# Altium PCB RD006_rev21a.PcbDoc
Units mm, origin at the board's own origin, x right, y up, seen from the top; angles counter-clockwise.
Board outline 20 x 20 mm, 2 copper layers (Top Layer, Bottom Layer), stack 1.569 mm thick; 25 components, 13 nets, 53 pads, 30 vias.
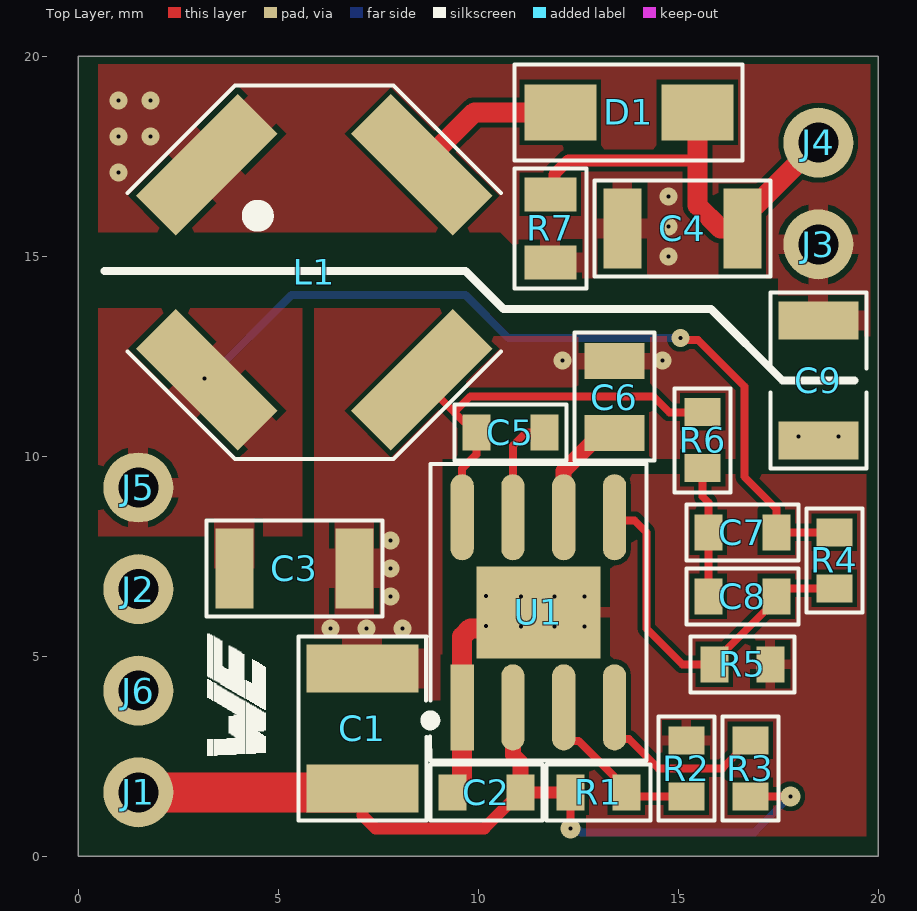
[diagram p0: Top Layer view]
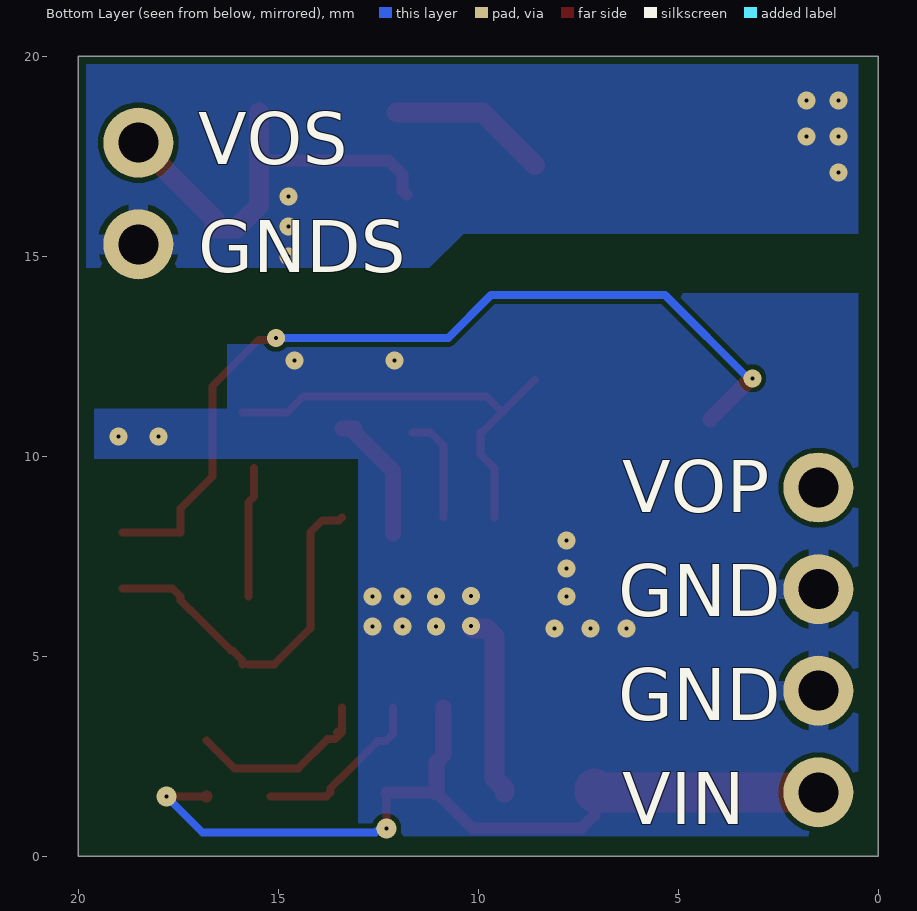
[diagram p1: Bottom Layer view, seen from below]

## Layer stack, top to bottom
Top Solder: solder mask 0.025, SM-001, Dk 4
Top Layer: signal copper 0.035
Dielectric 1: core 1.499, Core-043, Dk 4.3
Bottom Layer: signal copper 0.035
Bottom Solder: solder mask 0.025, SM-001, Dk 4

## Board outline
0,0 20,0 20,20 0,20

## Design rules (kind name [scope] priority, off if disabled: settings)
AcuteAngle [All] p1 off: minimum=4.50000000000000E+0001 checktracksonly=FALSE
AssemblyTestPointUsage [All] p1 off: valid=2
AssemblyTestpoint [All] p1 off: testpointundercomponent=TRUE minsize=1.016 maxsize=2.54 preferedsize=1.524 minholesize=0 maxholesize=1.016 preferedholesize=0.813 testpointgrid=0.025 usegrid=TRUE gridtolerance=0 allowsidetop=TRUE allowsidebottom=TRUE
Clearance Clearance_WEDirekt_125u_35u [All] p1: gap=0.125 ignorepadtopadclearanceinfootprint=TRUE except(0.17: SMDPad-SMDPad SMDPad-THPad THPad-THPad)
ComponentClearance "Schematic Component Clearance Constraint 2" [InComponent('NT1')] p1: gap=0 collisioncheckmode=3 verticalgap=0 showdistances=FALSE
ComponentClearance "Schematic Component Clearance Constraint 1" [InComponent('NT2')] p2: gap=0 collisioncheckmode=3 verticalgap=0 showdistances=FALSE
ComponentClearance ComponentClearance_ScrewToNut [(HasFootprint('NY PMS 440 0025 PH')) vs (HasFootprint('Keystone_1902C'))] p3: gap=0 collisioncheckmode=3 verticalgap=0 showdistances=FALSE
ComponentClearance ComponentClearance_testpoint [(HasFootprint('NO BOM TP'))] p4: gap=0 collisioncheckmode=3 verticalgap=0 showdistances=FALSE
ComponentClearance not_comp_1 [WithinRoom('not_comp')] p5: gap=0 collisioncheckmode=3 verticalgap=0 showdistances=FALSE
ComponentClearance ComponentClearance_1 [All] p6: gap=0.254 collisioncheckmode=3 verticalgap=0.254 showdistances=FALSE
ComponentClearance ComponentClearance_Shunt [InComponentClass('Header') vs InComponentClass('Shunt')] p7 off: gap=0 collisioncheckmode=3 verticalgap=0 showdistances=FALSE
ComponentClearance ComponentClearance_Logo [InComponentClass('Logo')] p8: gap=1.27 collisioncheckmode=3 verticalgap=0.254 showdistances=FALSE
ComponentClearance ComponentClearance_MountingHoles [InComponentClass('Mounting Holes')] p9: gap=0 collisioncheckmode=3 verticalgap=2540 showdistances=FALSE
ComponentClearance ComponentClearance_SmallPassives [HasFootprint('0201*') or HasFootprint('0402*') or HasFootprint('0508') or HasFootprint('0603*') or HasFootprint('0612') or HasFootprint('0805*') or HasFootprint('0815*') or HasFootprint('0830*') or HasFootprint('1206*') or HasFootprint('1210*') or HasFootprint('1808*') or HasFootprint('1812*') or HasFootprint('1825*') or HasFootprint('2010*') or HasFootprint('2220*') or HasFootprint('2225*') or HasFootprint('2512*') or HasFootprint('2728*') or HasFootprint('3518*') vs HasFootprint('0201*') or HasFootprint('0402*') or HasFootprint('0508') or HasFootprint('0603*') or HasFootprint('0612') or HasFootprint('0805*') or HasFootprint('0815*') or HasFootprint('0830*') or HasFootprint('1206*') or HasFootprint('1210*') or HasFootprint('1808*') or HasFootprint('1812*') or HasFootprint('1825*') or HasFootprint('2010*') or HasFootprint('2220*') or HasFootprint('2225*') or HasFootprint('2512*') or HasFootprint('2728*') or HasFootprint('3518*')] p10: gap=0.127 collisioncheckmode=3 verticalgap=0.254 showdistances=FALSE
ComponentClearance ComponentClearance_THtoSMT [IsThruComponent vs IsSMTComponent] p11: gap=1.016 collisioncheckmode=3 verticalgap=0.762 showdistances=FALSE
ComponentClearance ComponentClearance_THtoTH [IsThruComponent vs IsThruComponent] p12: gap=3 collisioncheckmode=3 verticalgap=0.762 showdistances=FALSE
DiffPairsRouting [All] p1 off: maxlimit=2.54 minlimit=0.254 mostfreqgap=0.254 toplayer_minwidth=0.381 toplayer_maxwidth=0.381 toplayer_prefwidth=0.381 bottomlayer_minwidth=0.381 bottomlayer_maxwidth=0.381 bottomlayer_prefwidth=0.381 maxuncoupledlength=25.4
FabricationTestPointUsage TestPointUsage [All] p1: valid=2 allowmultiple=FALSE
FabricationTestpoint Testpoint [All] p1: side=3 testpointundercomponent=TRUE minsize=1.016 maxsize=2.54 preferedsize=1.524 minholesize=0 maxholesize=1.016 preferedholesize=0.813 testpointgrid=0.025 allowsidetop=TRUE allowsidebottom=TRUE usegrid=TRUE gridtolerance=0
FanoutControl Fanout_LCC [IsLCC] p1 off: bgadir=Out bgaviamode=Centered fanoutstyle=Auto fanoutdirection=Alternating viagrid=0.025 // Fanout_LCC (Default Rule)
FanoutControl Fanout_BGA [IsBGA] p2: bgadir=Out bgaviamode=Centered fanoutstyle=Auto fanoutdirection=Alternating viagrid=0.025 // Fanout_BGA (Default Rule)
FanoutControl Fanout_Default [All] p4: bgadir=Out bgaviamode=Centered fanoutstyle=Auto fanoutdirection=Alternating viagrid=0.025 // Fanout_Default (Default Rule)
FanoutControl Fanout_Small [(CompPinCount < 5)] p5: bgadir=Out bgaviamode=Centered fanoutstyle=Auto fanoutdirection=OutThenIn viagrid=0.025 // Fanout_Small (Default Rule)
Height [All] p1 off: minheight=0 maxheight=25.4 prefheight=12.7
HoleSize [All] p1: absolutevalues=TRUE maxlimit=1000 minlimit=0.1 maxpercent=80.000 minpercent=20.000
HoleToHoleClearance [All] p1: gap=0.4 allowstackedmicrovias=TRUE
MinimumAnnularRing MinimumAnnularRing_ThermalPadVias [IsVia and InAnyComponent] p1: minimumring=0.174
MinimumAnnularRing [All] p2: minimumring=0.174
MinimumSolderMaskSliver MinimumSolderMaskSliver_Logo [InComponentClass('Logo') vs InComponentClass('Logo')] p1: minsoldermaskwidth=0.018
MinimumSolderMaskSliver [All] p2: minsoldermaskwidth=0.025
PlaneConnect [All] p1: planeconnectstyle=Direct reliefexpansion=0.254 reliefentries=4 reliefconductorwidth=0.254 reliefairgap=0.254
PolygonConnect PolygonConnect_1 [InNet('GND')] p1: connectstyle=Relief reliefconductorwidth=0.254 reliefentries=4 polygonreliefangle="90 Angle" airgapwidth=0.254
PolygonConnect [All] p2: connectstyle=Direct reliefconductorwidth=0.254 reliefentries=4 polygonreliefangle="90 Angle" airgapwidth=0.254
RoutingVias Vias_WEDirekt_125u_35u [IsVia and InAnyComponent] p1: holewidth=0.1 width=0.45 viastyle="Through Hole" minholewidth=0.1 minwidth=0.45 maxholewidth=1 maxwidth=20
RoutingVias [All] p2: holewidth=0.1 width=0.45 viastyle="Through Hole" minholewidth=0.1 minwidth=0.45 maxholewidth=20 maxwidth=20
SMDToCorner [All] p1: distance=30000
SilkToSilkClearance [All] p1 off: silktosilkclearance=0.127
SilkToSolderMaskClearance SilkscreenOverComponentPads [IsPad] p1 off: minsilkscreentomaskgap=0.127 clearancetoexposedcopper=TRUE
SolderMaskExpansion [All] p1: expansion=0.1 istentingtop=FALSE
UnRoutedNet [All] p1: checkbadconnections=TRUE
Width Width_WEDirekt_125u_35u [All] p1: maxlimit=20 minlimit=0.125 preferedwidth=0.5 minimp=50.000000 maximp=50.000000 favimp=50.000000 checkconnectedcopper=TRUE
12 further rules are at their usual default settings.

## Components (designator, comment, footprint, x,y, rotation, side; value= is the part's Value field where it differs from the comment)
C1 "885012209048" C1210 7.1,3.2 r270 top value=4.7u
C2 "885012206121" C0603 10.2,1.6 r0 top value=330n
C3 "885012208019" C1206 5.4,7.2 r180 top value=22u
C4 "885012208019" C1206 15.1,15.7 r180 top value=22u
C5 "885012206065" C0603 10.8,10.6 r180 top value=10n
C6 "885012207023" C0805 13.4,11.48 r270 top value=1.5u
C7 "885012206087" C0603 16.6,8.1 r0 top value=4.7n
C8 "885012206095" C0603 16.6,6.5 r180 top value=100n
C9 "885342208024" C1206 18.5,11.9 r90 top value=1n
D1 "SS1FN6-M3" D_DO-219AB_(SMF) 13.7,18.6 r0 top
J1 "Pin_hole_1mm" J_PIN-TH-ROUND-1MM#1 1.5,1.6 r90 top
J2 "Pin_hole_1mm" J_PIN-TH-ROUND-1MM#2 1.5,7.067 r90 top
J3 "Pin_hole_1mm" J_PIN-TH-ROUND-1MM#1 18.5,15.3 r90 top
J4 "Pin_hole_1mm" J_PIN-TH-ROUND-1MM#3 18.5,18.1 r90 top
J5 "Pin_hole_1mm" J_PIN-TH-ROUND-1MM#4 1.5,9.8 r90 top
J6 "Pin_hole_1mm" J_PIN-TH-ROUND-1MM#5 1.5,4.333 r90 top
L1 "76889440330" "WE-TDC HV_8038" 5.9,14.6 r45 top value="33 uH"
R1 "RC0603FR-07127KL" R0603 13,1.6 r180 top value=127k
R2 "RC0603FR-0715K4L" R0603 15.2,2.2 r270 top value=15.4k
R3 "RT0603BRD07120KL" R0603 16.8,2.2 r90 top value=120k
R4 "RT0603DRE074K7L" R0603 18.9,7.4 r90 top value=4.7k
R5 "RT0603DRD071K5L" R0603 16.6,4.8 r180 top value=1.5k
R6 "RC0603FR-1033KL" R0603 15.61,10.41 r270 top value=33k
R7 "RCS0805300RJNEA" R0805 11.8,15.7 r270 top value=300
U1 "LM25017" IC_SOIC-8-DDA0008J 11.5,6.1 r90 top

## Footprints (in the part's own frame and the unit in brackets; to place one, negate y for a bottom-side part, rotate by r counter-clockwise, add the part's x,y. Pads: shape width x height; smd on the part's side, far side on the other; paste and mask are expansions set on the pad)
C0603 [mm] "R0603"
  rect 0.7x0.9 smd: 1(-0.85,0) 2(0.85,0)
  body extent -0.8,-0.4 0.8,0.4, height 0.6
C0805 [mm] "Chip Capacitor, 2-Leads, Body 2.00x1.25mm, IPC Low Density"
  rect 0.9x1.5 smd: 1(-0.9,0) 2(0.9,0)
  body extent -1.1,-0.72 1.1,0.72, height 1.45
C1206 [mm]
  rect 0.95x2 smd: 1(-1.5,0) 2(1.5,0)
  body extent -1.7,-0.9 1.7,0.9, height 1.8
C1210 [mm] "Chip Capacitor, Body 3.2x2.5mm, Height 2.8mm, IPC High Density"
  rect 1.2x2.8 smd: 1(-1.5,0) 2(1.5,0)
  body extent -1.7,-1.4 1.7,1.4, height 2.8
D_DO-219AB_(SMF) [mm]
  rect 1.8x1.4 smd: A(-1.651,0) C(1.778,0)
  body extent -1.95,-0.95 1.95,0.95, height 1.08
IC_SOIC-8-DDA0008J [mm]
  rect 2.153x0.582 smd paste+0 mask+0: 1(-2.377,1.905)
  rrect100% 2.153x0.582 smd paste+0 mask+0: 2(-2.377,0.635) 3(-2.377,-0.635) 4(-2.377,-1.905) 5(2.377,-1.905) 6(2.377,-0.635) 7(2.377,0.635) 8(2.377,1.905)
  rect 2.3x3.1 smd paste-1000 mask+0: 9(0,0)
  silkscreen extent -2.82,2.57 -2.58,2.82, body extent -3.7,-2.7 3.7,2.7, height 0.25
J_PIN-TH-ROUND-1MM#1 [mm] "PIN-TH-ROUND-1MM"
  round 1.75 / inner round 1.524 / far side round 1.75 hole 1: 1(0,0)
J_PIN-TH-ROUND-1MM#2 [mm] "PIN-TH-ROUND-1MM"
  round 1.75 / inner round 1.524 / far side round 1.75 hole 1: 1(-0.387,0)
J_PIN-TH-ROUND-1MM#3 [mm] "PIN-TH-ROUND-1MM"
  round 1.75 / inner round 1.524 / far side round 1.75 hole 1: 1(-0.26,0)
J_PIN-TH-ROUND-1MM#4 [mm] "PIN-TH-ROUND-1MM"
  round 1.75 / inner round 1.524 / far side round 1.75 hole 1: 1(-0.58,0)
J_PIN-TH-ROUND-1MM#5 [mm] "PIN-TH-ROUND-1MM"
  round 1.75 / inner round 1.524 / far side round 1.75 hole 1: 1(-0.193,0)
R0603 [mm] "Chip Resistor, Body 1.6x0.8mm, IPC High Density"
  rect 0.7x0.9 smd: 1(-0.7,0) 2(0.7,0)
  body extent -0.85,-0.47 0.85,0.47, height 0.6
R0805 [mm] "Chip Resistor, Body 2.0x1.3mm, IPC High Density"
  rect 0.85x1.3 smd: 1(-0.85,0) 2(0.85,0)
  body extent -1.1,-0.67 1.1,0.68, height 0.7
"WE-TDC HV_8038" [mm] "SMD Coupled Inductor, 4-leads, body 8x8mm"
  rect 3.6x1.4 smd: 1(0,3.8) 3(0,-3.8)
  rect 1.4x3.6 smd: 2(-3.8,0) 4(3.8,0)
  silkscreen extent -0.2,1.8 0.2,2.2, body extent -4,-4 4,4, height 3.8

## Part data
C1: "MLCC WCAP-CSGP General Purpose 4.7uF 10% 50V X7R SMD-1210 885012209048", Dielectric=X7R, MFR="Wurth Elektronik", Package=1210, Tolerance=10%, Voltage=50V
C2: "MLCC WCAP-CSGP General Purpose 330nF 10% 50V X7R SMD-0603 885012206121", Dielectric=X7R, MFR="Wurth Elektronik", Package=0603, Tolerance=10%, Voltage=50V
C3 C4: "MLCC WCAP-CSGP General Purpose 22uF 10% 10V X7R SMD-1206 885012208019", Dielectric=X7R, MFR="Wurth Elektronik", Package=1206, Tolerance=10%, Voltage=10V
C5: "MLCC WCAP-CSGP General Purpose 10nF 10% 25V X7R SMD-0603 885012206065", Dielectric=X7R, MFR="Wurth Elektronik", Package=0603, Tolerance=10%, Voltage=25V
C6: "MLCC WCAP-CSGP General Purpose 1.5uF 10% 10V X7R SMD-0805 885012207023", Dielectric=X7R, MFR="Wurth Elektronik", Package=0805, Tolerance=10%, Voltage=10V
C7: "MLCC WCAP-CSGP General Purpose 4.7nF 10% 50V X7R SMD-0603 885012206087", Dielectric=X7R, MFR="Wurth Elektronik", Package=0603, Tolerance=10%, Voltage=50V
C8: "MLCC WCAP-CSGP General Purpose 100nF 10% 50V X7R SMD-0603 885012206095", Dielectric=X7R, MFR="Wurth Elektronik", Package=0603, Tolerance=10%, Voltage=50V
C9: "MLCC WCAP-CSGP HIgh-voltage 1nF 10% 2000V X7R SMD-1206 885342208024", Dielectric=X7R, MFR="Wurth Elektronik", Package=1206, Tolerance=10%, Voltage=2000V
D1: "Schottky Rectifier 1A 60V SMD SMF (DO-219AB) SS1FN6-M3", Current=1A, MFR=Vishay, Package="DO-219AB (SMF)", Voltage=60V
J1 J2 J3 J4 J5 J6: "Pin Hole 1mm"
L1: library part "TDC-HV 8038 76889440330", "TDC-HV 8038 33uH 1.85A 1:1 SMD Coupled Inductor 76889440330", MFR="Wurth Elektronik"
R1: "Thick Film 127k 1% 100mW SMD-0603 RC0603FR-07127KL", MFR=Yageo, Package=0603, Power=100mW, Tolerance=1%
R2: "Thick Film 15.4k 1% 100mW SMD-0603 RC0603FR-0715K4L", MFR=Yageo, Package=0603, Power=100mW, Tolerance=1%
R3: "Thin Film 120k 0.1% 100mW SMD-0603 RT0603BRD07120KL", MFR=Yageo, Package=0603, Power=100mW, Tolerance=0.1%
R4: "Thin Film 4.7k 0.1% 100mW SMD-0603 RT0603DRE074K7L", MFR=Yageo, Package=0603, Power=100mW, Tolerance=0.1%
R5: "Thin Film 1.5k 0.1% 100mW SMD-0603 RT0603DRD071K5L", MFR=Yageo, Package=0603, Power=100mW, Tolerance=0.1%
R6: "Thick Film 33k 1% 100mW SMD-0603 RC0603FR-1033KL", MFR=Yageo, Package=0603, Power=100mW, Tolerance=1%
R7: "Thick Film 300 5% 400mW SMD-0805 RCS0805300RJNEA", MFR=Yageo, Package=0603, Power=400mW, Tolerance=5%
U1: "IC Synchronous Buck/Flybuck Controller 48V 0.65A LM25017 SMD SOIC-8 Texas Instruments", MFR="Texas Instruments", Package=SOIC-8

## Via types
v1: diameter 0.45, hole 0.1, Top Layer to Bottom Layer, 28 vias
v2: diameter 0.5, hole 0.1, Top Layer to Bottom Layer, 2 vias

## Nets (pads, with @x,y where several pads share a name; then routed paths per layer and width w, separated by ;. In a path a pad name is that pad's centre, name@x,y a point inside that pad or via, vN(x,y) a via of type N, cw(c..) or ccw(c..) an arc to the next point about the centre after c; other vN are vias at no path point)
BST: C5.1 U1.7 | length 2.7
  Top Layer w0.2: U1.7 10.865,10.265 11.2,10.6 C5.1
DSEC: D1.A L1.4 | length 4
  Top Layer w0.5: L1.4 9.9,18.6 D1.A
FB: C8.1 R4.1 R5.2 U1.5 | length 9.2
  Top Layer w0.2: U1.5 13.482,8.4 13.9,8.4 14.2,8.1 14.2,5.7 15.1,4.8 R5.2@15.75,4.8 ; R5.2 15.9,4.9 16.15,5.15 16.187,5.15 17.187,6.15 17.2,6.15 17.45,6.4 C8.1 17.65,6.7 R4.1
GND: C1.1 C2.1 C3.1 C6.1 C9.1 J2.1 J6.1 R2.1 R5.1 U1.1 U1.9 | length 4.7
  Top Layer w0.2: U1.9@10.136,5.7 v1(10.188,5.752)
  Top Layer w0.5: C2.1 9.35,1.7 9.595,1.945 U1.1 9.595,5.495 9.8,5.7 U1.9@10.136,5.7
  other v1: 6.3,5.7 7.2,5.7 8.1,5.7 11.064,5.747 11.9,5.75 12.65,5.75 7.8,6.5 10.188,6.502 11.064,6.497 11.9,6.5 12.65,6.5 7.8,7.2 7.8,7.9 18,10.5 19,10.5 12.1,12.4 14.6,12.4
GND_ISO: C4.2 C9.2 J3.1 L1.1 R7.2
  other v1: 14.75,15 14.75,15.75 14.75,16.5 1,17.1 1,18 1.8,18 1,18.9 1.8,18.9
RON: R3.2 U1.4 | length 4.7
  Top Layer w0.2: U1.4 13.405,3.104 13.582,2.928 13.772,2.928 14.5,2.2 16.1,2.2 R3.2 ; U1.4@13.505,3.123 U1.4@13.528,3.1
SW: C5.2 L1.3 R6.1 U1.8 | length 11
  Top Layer w0.2: L1.3 9.4,11.1 ; U1.8 9.595,9.695 9.95,10.05 C5.2 9.9,10.6 9.4,11.1 ; R6.1@15.9,11.1 14.776,11.1 14.376,11.5 9.8,11.5 9.4,11.1
UVLO: R1.1 R2.2 U1.3 | length 4.4
  Top Layer w0.2: U1.3 12.135,3.064 12.312,2.887 12.502,2.887 13.44,1.95 13.45,1.95 13.7,1.7 R1.1 13.8,1.5 R2.2
VCC: C6.2 U1.6 | length 3.2
  Top Layer w0.4: U1.6@12.135,8.077 12.135,9.635 C6.2@13.1,10.6 ; C6.2@13.1,10.7 C6.2@13.4,10.7
VIN: C1.2 C2.2 J1.1 R1.2 R3.1 U1.2 | length 22
  Top Layer w0.2: v2(12.3,0.7) R1.2 ; R3.1 v2(17.8,1.5)
  Top Layer w0.3: C1.2@7.1,1.6 7.1,1.024 7.424,0.7 10.15,0.7 C2.2 R1.2
  Top Layer w0.4: U1.2 10.865,2.535 11.05,2.35 C2.2
  Top Layer w1: J1.1 7.1,1.6 C1.2
  Bottom Layer w0.2: v2(12.3,0.7) 12.357,0.643 12.525,0.643 12.567,0.6 16.9,0.6 v2(17.8,1.5)
VOUT: C3.2 C7.2 J5.1 L1.2 R4.2 | length 22.1
  Top Layer w0.2: v1(15.06,12.96) 15.108,12.912 15.488,12.912 16.65,11.75 16.65,9.49 17.45,8.69 C7.2 R4.2
  Top Layer w0.4: L1.2 L1.2@4.2,10.926
  Bottom Layer w0.2: v1@3.2,11.9 5.33,14.03 9.68,14.03 10.75,12.96 v1(15.06,12.96)
  other v1: 3.15,11.95
VOUT_ISO: C4.1 D1.C J4.1 R7.1 | length 10.9
  Top Layer w0.3: R7.1 11.9,16.65 11.9,17.051 12.249,17.4 15.478,17.4
  Top Layer w0.5: D1.C 15.478,17.4 15.478,16.271 16.049,15.7 C4.1 16.6,15.94 J4.1
VR: C7.1 C8.2 R6.2 | length 3.3
  Top Layer w0.2: R6.2 15.61,8.99 15.75,8.85 C7.1 C8.2

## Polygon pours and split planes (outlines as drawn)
GND on Bottom Layer "GND_BOT_PWR" (solid, pour order 78): 9.634,14.076 10.91,12.8 16.275,12.8 16.275,11.19 19.6,11.19 19.6,9.933 13,9.933 13,0.5 0.5,0.5 0.5,14.076
GND_ISO on Bottom Layer "GND_ISO_BOT" (solid, pour order 72): 0.5,15.57 10.365,15.57 11.225,14.71 18.25,14.71 19.8,14.71 19.8,19.8 0.5,19.8
GND on Top Layer "GND_TOP_SGN" (solid, remove dead copper, pour order 77): 12.7,9.55 19.7,9.55 19.7,0.5 14.6,0.5 12.7,0.5
GND on Top Layer "GND_TOP_PWR" (solid, pour order 79): 9.1,9.933 9.1,3.9 5.9,3.9 5.9,13.7 9.4,13.7 10.1,13 16.9,13 16.9,11.9 16.9,9.933
VOUT on Top Layer "VOUT_TOP" (solid, pour order 76): 0.5,8 5.6,8 5.6,13.7 0.5,13.7
GND_ISO on Top Layer "GND_ISO_TOP" (solid, pour order 71): 0.5,15.6 10.545,15.6 11.695,14.45 17.5,14.45 17.5,13 19.8,13 19.8,19.8 0.5,19.8

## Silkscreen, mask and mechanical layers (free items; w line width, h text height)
Top Overlay:
  drawing of 251 lines, arcs and shapes, not listed
Bottom Overlay:
  text "VOS" at 17,17.3 h1.3
  text "GNDS" at 17,14.6 h1.3
  text "VOP" at 6.4,8.6 h1.3
  text "GND" at 6.5,6 h1.3
  text "GND" at 6.5,3.4 h1.3
  text "VIN" at 6.4,0.8 h1.3
Board Outline:
  the board outline again, w0.1
Dimensions:
  text "Dimensions in MM" at -5.2,25.3 h2
  text "Dimensions" at 1.58,-20.6 h2
Bottom Reference_Assembly:
  lines w0.127: 340.9,27.585 345.98,27.585 ; 340.9,98.07 345.98,98.07 ; 340.9,168.555 345.98,168.555
  text "A" at 342.805,201.626 h1.78
  text "B" at 342.805,131.014 h1.78
  text "C" at 342.805,60.402 h1.78
  text "D" at 342.805,-9.702 h1.78
Drill Drawing:
  circle w0.254: c-13.693,47.421 r0.866
  lines w0.254: -14.558,50.45 -12.827,50.45 -12.827,52.182 -14.558,52.182 -14.558,50.45
  lines w0.381: -16.11,45.386 164.248,45.386 ; -16.11,53.177 164.248,53.177 ; -1.821,41.491 -1.821,57.073 ; 12.188,41.491 12.188,57.073 ; 40.477,41.491 40.477,57.073 ; 53.597,41.491 53.597,57.073 ; 72.636,41.491 72.636,57.073 ; 111.569,41.491 111.569,57.073 ; 126.87,41.491 126.87,57.073 ; 146.221,41.491 146.221,57.073 ; -16.11,41.491 164.248,41.491 164.248,57.073 -16.11,57.073 -16.11,41.491
  text "Symbol" at -13.772,54.346 h1.87
  text "Count" at -0.652,54.346 h1.87
  text "Hole Size" at 13.357,54.346 h1.87
  text "Plated" at 41.646,54.346 h1.87
  text "Hole Type" at 54.765,54.346 h1.87
  text "Drill Layer Pair" at 73.805,54.346 h1.87
  text "Via/Pad" at 112.738,54.346 h1.87
  text "Pad Shape" at 128.039,54.346 h1.87
  text "Template" at 147.389,54.346 h1.87
  text "6" at -0.652,50.45 h1.56
  text "1.000mm (39.37mil)" at 13.357,50.45 h1.56
  text "PTH" at 41.646,50.45 h1.56
  text "Round" at 54.765,50.45 h1.56
  text "Top Layer - Bottom Layer" at 73.805,50.45 h1.56
  text "Pad" at 112.738,50.45 h1.56
  text "Rounded" at 128.039,50.45 h1.56
  text "(Mixed)" at 147.389,50.45 h1.56
  text "30" at -0.652,46.555 h1.56
  text "0.100mm (3.94mil)" at 13.357,46.555 h1.56
  text "PTH" at 41.646,46.555 h1.56
  text "Round" at 54.765,46.555 h1.56
  text "Top Layer - Bottom Layer" at 73.805,46.555 h1.56
  text "Via" at 112.738,46.555 h1.56
  text "Rounded" at 128.039,46.555 h1.56
  text "(Mixed)" at 147.389,46.555 h1.56
  text "36 Total" at -0.652,42.659 h1.56
  text "DRILL Guide" at 5.28,-20.65 h2
Sheet:
  drawing of 1218 lines, arcs and shapes, not listed
  text "1" at -23.683,235.611 h1.78
  text "2" at 25.356,235.611 h1.78
  text "3" at 74.615,235.611 h1.78
  text "4" at 123.908,235.611 h1.78
  text "5" at 173.184,235.611 h1.78
  text "6" at 222.206,235.611 h1.78
  text "7" at 271.736,235.611 h1.78
  text "8" at 320.758,235.611 h1.78
  text "A" at -45.815,201.626 h1.78
  text "B" at -45.815,131.014 h1.78
  text "C" at -45.815,60.402 h1.78
  text "D" at -45.815,-9.702 h1.78
  text "TITLE:" at 200.28,-18.9 h2
  text "RD006 board" at 211.28,-18.9 h2
  text "Eleazar Falco" at 215.28,-24.65 h2
  text "ENGINEER:" at 200.28,-24.9 h2
  text "August 21" at 210.28,-30.9 h2
  text "DATE:" at 200.28,-31 h2
  text "N/A" at 213.53,-36.4 h2
  text "REV:" at 232.78,-36.4 h2
  text "21a" at 240.53,-36.4 h2
  text "N/A" at 280.53,-36.4 h2
  text "VERSION:" at 200.28,-36.5 h2
  text "ASSY VARIANT:" at 258.18,-36.5 h2
  text "1" at -23.683,-41.249 h1.78
  text "2" at 25.356,-41.249 h1.78
  text "3" at 74.615,-41.249 h1.78
  text "4" at 123.908,-41.249 h1.78
  text "5" at 173.184,-41.249 h1.78
  text "6" at 222.206,-41.249 h1.78
  text "7" at 271.736,-41.249 h1.78
  text "8" at 320.758,-41.249 h1.78
Gerber Print:
  drawing of 1652 lines, arcs and shapes, not listed
  text "ARTWORK VIEWED FROM TOP SIDE OF BOARD" at -1.47,-12.4 h1.6
  text "BOARD NAME:" at -11.72,-16.65 h2
  text "RD006 Board" at 11.28,-16.65 h2
  text "LAYER:" at -11.72,-20.9 h2
  text "REV:" at 21.78,-24.9 h2
  text "21a" at 31.78,-24.9 h2
  text "VERSION:" at -11.72,-25.15 h2
  text "N/A" at 4.78,-25.15 h2
  text "DATE:" at -11.72,-29.4 h2
  text "August 21" at -0.8,-30.2 h2
  text "(c) Wurth Elektronik eiSos Group        www.we-online.de" at -12.72,-33.9 h2
Assembly Notes:
  drawing of 365 lines, arcs and shapes, not listed
  text "FABRICATION NOTES" at 247.33,214.6 h3
  text "Layer" at -14.721,212.024 h1.72
  text "Name" at -3.068,212.024 h1.72
  text "Material" at 34.874,212.024 h1.72
  text "Thickness" at 57.958,212.024 h1.72
  text "Constant" at 76.469,212.024 h1.72
  text "Board Layer Stack" at 92.694,212.024 h1.72
  text "Top Overlay" at -3.068,208.594 h1.72
  text "Top Solder" at -3.068,205.163 h1.72
  text "SM-001" at 34.874,205.163 h1.72
  text "0.025mm" at 57.958,205.163 h1.72
  text "4" at 76.469,205.163 h1.72
  text "MINIMUM SIZE CONSTRAINTS" at 248.03,204.6 h2
  text "Top Surface Finish" at -3.068,201.733 h1.72
  text "Nickel, Gold" at 34.874,201.733 h1.72
  text "0.004mm" at 57.958,201.733 h1.72
  text "1" at -14.721,198.303 h1.72
  text "Top Layer" at -3.068,198.303 h1.72
  text "CF-004" at 34.874,198.303 h1.72
  text "0.035mm" at 57.958,198.303 h1.72
  text "TRACK WIDTH (MIN):" at 217.03,196.6 h2
  text "0.2 mm" at 255.03,196.6 h2
  text "CLEARANCE (MIN):" at 277.03,196.6 h2
  text "0.125 mm" at 312.03,196.6 h2
  text "Dielectric 1" at -3.068,194.873 h1.72
  text "Core-043" at 34.874,194.873 h1.72
  text "1.499mm" at 57.958,194.873 h1.72
  text "4.3" at 76.469,194.873 h1.72
  text "2" at -14.721,191.443 h1.72
  text "Bottom Layer" at -3.068,191.443 h1.72
  text "CF-004" at 34.874,191.443 h1.72
  text "0.035mm" at 57.958,191.443 h1.72
  text "DRILL DIAM.(MIN):" at 217.03,188.6 h2
  text "0.1 mm" at 255.03,188.6 h2
  text "PAD SIZE (MIN):" at 277.03,188.6 h2
  text "XXXX mm" at 312.03,188.6 h2
  text "Bottom Surface Finish" at -3.068,188.013 h1.72
  text "Nickel, Gold" at 34.874,188.013 h1.72
  text "0.004mm" at 57.958,188.013 h1.72
  text "Bottom Solder" at -3.068,184.583 h1.72
  text "SM-001" at 34.874,184.583 h1.72
  text "0.025mm" at 57.958,184.583 h1.72
  text "4" at 76.469,184.583 h1.72
  text "Bottom Overlay" at -3.068,181.153 h1.72
  text "Total board thickness:" at -14.721,177.723 h1.72
  text "1.627mm" at 57.958,177.723 h1.72
  text "EXTERNAL" at 306.03,177.6 h2
  text "ANNULAR RING DIAMETER (MIN):" at 217.03,176.6 h2
  text "0.45 mm" at 278.9,176.3 h2
  text "INTERNAL" at 306.03,173.6 h2
  text "VIAS DETAILS:" at 217.03,163.6 h2
  text "x" at 250.891,163.503 h2
  text "VIAS IN PAD" at 255.03,162.6 h2
  text "CONDUCTIVE FILL" at 292.03,159.6 h2
  text "TENTED VIAS" at 255.03,157.6 h2
  text "NON-CONDUCTIVE FILL" at 292.03,155.6 h2
  text "FILLED VIAS" at 255.03,152.6 h2
  text "FURTHER VIA DETAILS IN DRAWING ATTACHED" at 217.03,143.6 h2
  text "DRILL AND HOLES DETAILS SEE ADJACENT TABLE" at 217.03,139.6 h2
  text "SUBSTRATE MATERIAL AND LAYER STACK-UP SEE ADJACENT TABLE" at 217.03,135.6 h2
  text "SURFACE FINISH PLATING" at 217.03,127.6 h2
  text "ENIG" at 227.03,119.6 h2
  text "ImAg" at 251.53,119.6 h2
  text "ImSn" at 276.03,119.6 h2
  text "OTHER:" at 294.03,119.6 h2
  text "x" at 222.8,119.5 h2
  text "SOLDER MASK COLOR:" at 217.03,109.6 h2
  text "x" at 222.83,102.4 h2
  text "RED" at 227.03,101.6 h2
  text "GREEN" at 251.53,101.6 h2
  text "BLUE" at 276.03,101.6 h2
  text "OTHER:" at 294.03,101.6 h2
  text "x" at 271.88,94.3 h2
  text "FINISH:" at 223.03,93.6 h2
  text "MATTE" at 251.53,93.6 h2
  text "GLOSS" at 276.03,93.6 h2
  text "OTHER:" at 294.03,93.6 h2
  text "SILKSCREEN:" at 230.03,84.6 h2
  text "SILKSCREEN COLOR:" at 274.03,84.6 h2
  text "x" at 222.93,78.5 h2
  text "x" at 240.93,78.5 h2
  text "TOP" at 227.03,77.6 h2
  text "BOTTOM" at 245.03,77.6 h2
  text "WHITE" at 275.03,77.6 h2
  text "OTHER:" at 294.03,77.6 h2
  text "x" at 270.83,77.4 h2
  text "NOTES:" at 225.03,68.6 h2
  text "SILKSCREEN LOCATION AS PER GERBER FILE" at 240.03,68.6 h2
  text "NO SILKSCREEN ON EXPOSED CONDUCTIVE PADS" at 240.03,64.6 h2
  text "USE PERMANENT NON-CONDUCTIVE INK" at 240.03,60.6 h2
  text "ARRAY-PANELIZATION CUT-OUT" at 247.03,51.6 h2
  text "x" at 283.88,45.5 h2
  text "V-SCORE" at 227.03,44.6 h2
  text "NC-ROUTE" at 258.03,44.6 h2
  text "LOOSE (CUT AND TRIM)" at 288.03,44.6 h2
  text "x" at 286.83,36.4 h2
  text "ELECTRICAL TEST REQUIRED:" at 217.03,35.6 h2
  text "YES" at 291.03,35.6 h2
  text "NO" at 309.03,35.6 h2
  text "ADDITIONAL REQUIREMENTS NOT SPECIFIED SHALL MEET OR EXCEED IPC-6012 CLASS-B SPECIFICATION" at 216.78,25.022 h2 r0.04
  text "ACCEPTANCE CRITERIA AS PER IPC-600 CLASS B" at 217.03,22.1 h2
  text "RoHS COMPLIANCE" at 217.28,19.1 h2
  text "ADDITIONAL INFORMATION:" at 221.28,10.1 h2
Top-Route_Print_Gerber:
  text "TOP Route" at 2.28,-20.9 h2
Bottom-Route_Print_Gerber:
  text "BOTTOM Route" at 2.38,-20.9 h2
TopPaste_Print_Gerber:
  text "TOP Paste" at 2.28,-20.9 h2
BottomPaste_Print_Gerber:
  text "BOTTOM Paste" at 2.28,-20.9 h2
TopSolder_Print_Gerber:
  text "TOP Soldermask" at 2.28,-20.9 h2
BottomSolder_Print_Gerber:
  text "BOTTOM Soldermask" at 2.28,-20.9 h2
Top_Reference_Print_Gerber:
  text "TOP Assembly Reference" at 2.28,-20.9 h2
Top_Silkscreen_Print_Gerber:
  text "TOP Silkscreen" at 2.28,-20.65 h2
Bottom_Silkscreen_Print_Gerber:
  text "BOTTOM Silkscreen" at 2.28,-20.9 h2
Bottom_Reference_Print_Gerber:
  text "BOTTOM Assembly Reference" at 2.28,-20.9 h2
V-Cut_Print:
  text "V-Cut Guide" at 1.28,-20.9 h2
Dimensions_Print:
  text "Board Dimensions" at 1.08,-21 h2

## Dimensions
0,0 to 0,20 on Dimensions
0,0 to 20,0 on Dimensions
